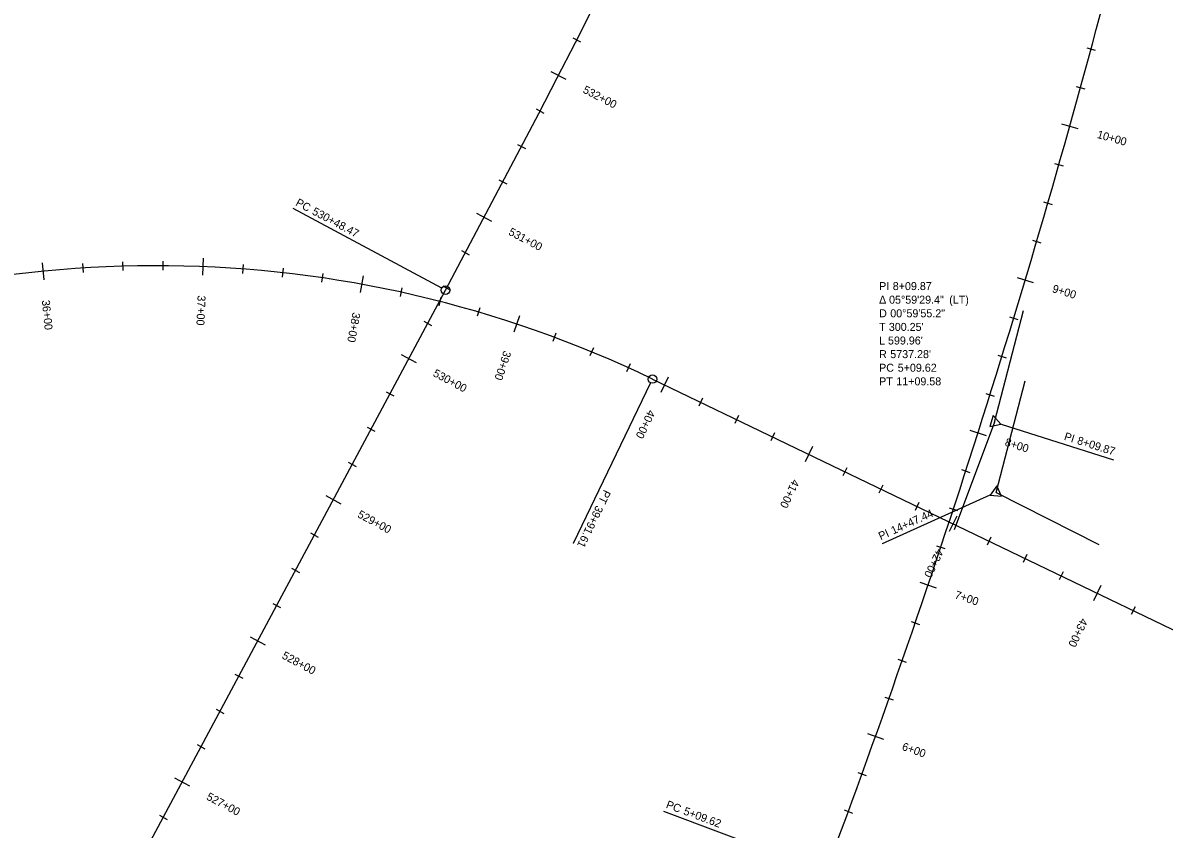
# Model space of a CAD drawing. Extents: x 2300830 to 2307917, y 756066 to 766359.
# Drawn here: x 2303533 to 2304246, y 761628 to 762132 of the extents above; entities that cross this region are included whole.
import ezdxf

# ---------------------------------------------------------------- set-up
doc = ezdxf.new("R2010")
doc.units = 0
for name, color, linetype in [('Default', 7, 'Continuous'), ('Draft_Curve Data Label', 7, 'Continuous'), ('Draft_Station Cardinal Lines', 7, 'Continuous'), ('Draft_Station Cardinal Points', 7, 'Continuous'), ('Draft_Station Labels Major', 7, 'Continuous'), ('Draft_Station Ticks Major', 7, 'Continuous'), ('Draft_Station Ticks Minor', 7, 'Continuous'), ('Geom_Baseline', 7, 'Continuous')]:
    doc.layers.add(name, color=color, linetype=linetype)

msp = doc.modelspace()

# ---------------------------------------------------------------- linework, layer by layer
at = {"layer": 'Default'}
for p, q in [((2301469.01, 757616.61), (2303797.09, 761964.97)), ((2301469.01, 757616.61), (2303797.09, 761964.97)), ((2303926.45, 761909.44), (2305518.87, 761142.43))]:
    msp.add_line(p, q, dxfattribs=at)
for centre, radius, start, end in [((2294501.04, 766942.01), 10544.55, 331.835697, 340.516399), ((2304169.7, 761693.02), 983.53, 137.61666, 272.52241), ((2298662.99, 763616.57), 5737.28, 339.437219, 345.42872), ((2303616.31, 761265.54), 714.7, 64.28167, 164.6807)]:
    msp.add_arc(centre, radius, start, end, dxfattribs=at)
at = {"layer": 'Draft_Station Cardinal Lines'}
for p, q in [((2303794.74, 761966.23), (2303701.88, 762015.94)), ((2304140.2, 761882.57), (2304158.31, 761952.25)), ((2303925.29, 761907.03), (2303876.98, 761806.73)), ((2304141.13, 761838.6), (2304159.25, 761908.29)), ((2304140.2, 761882.57), (2304114.91, 761815.16)), ((2304144.2, 761881.3), (2304214.56, 761859.03)), ((2304137.31, 761836.88), (2304070.03, 761806.54)), ((2304141.13, 761838.6), (2304205.36, 761806.05)), ((2304032.24, 761602.39), (2303933.62, 761639.38))]:
    msp.add_line(p, q, dxfattribs=at)
for points in [[(2304144.16, 761881.32), (2304139.3, 761886.63), (2304137.13, 761879.77)], [(2304137.34, 761836.89), (2304144.51, 761836.18), (2304141.55, 761842.74)]]:
    msp.add_lwpolyline(points, close=True, dxfattribs=at)
at = {"layer": 'Draft_Station Cardinal Points'}
for p, q in [((2303701.88, 762015.94), (2303701.88, 762015.94)), ((2303797.09, 761964.97), (2303797.09, 761964.97)), ((2303926.45, 761909.44), (2303926.45, 761909.44)), ((2304140.2, 761882.57), (2304140.2, 761882.57)), ((2304214.56, 761859.03), (2304214.56, 761859.03)), ((2304141.13, 761838.6), (2304141.13, 761838.6)), ((2303876.98, 761806.73), (2303876.98, 761806.73)), ((2304070.03, 761806.54), (2304070.03, 761806.54)), ((2303933.62, 761639.38), (2303933.62, 761639.38))]:
    msp.add_line(p, q, dxfattribs=at)
for centre in [(2303797.09, 761964.97), (2303926.45, 761909.44)]:
    msp.add_circle(centre, 2.67, dxfattribs=at)
at = {"layer": 'Draft_Station Ticks Major'}
for p, q in [((2303862.91, 762101.52), (2303872.34, 762096.64)), ((2304182.02, 762068.82), (2304192.24, 762065.95)), ((2303816.58, 762012.95), (2303825.97, 762007.98)), ((2303545.09, 761982.05), (2303546.14, 761971.48)), ((2303645.71, 761984.98), (2303645.28, 761974.37)), ((2303745.76, 761973.84), (2303743.85, 761963.4)), ((2304154.2, 761972.87), (2304164.38, 761969.82)), ((2303843.28, 761948.87), (2303839.93, 761938.79)), ((2303769.51, 761924.75), (2303778.87, 761919.74)), ((2303936.32, 761910.61), (2303931.72, 761901.04)), ((2304124.72, 761877.41), (2304134.84, 761874.19)), ((2304026.42, 761867.21), (2304021.81, 761857.65)), ((2303722.31, 761836.59), (2303731.67, 761831.58)), ((2304116.51, 761823.82), (2304111.9, 761814.25)), ((2304093.58, 761782.48), (2304103.64, 761779.08)), ((2304206.61, 761780.42), (2304202, 761770.86)), ((2303675.11, 761748.43), (2303684.47, 761743.42)), ((2304060.79, 761688.11), (2304070.79, 761684.54)), ((2303627.91, 761660.27), (2303637.27, 761655.26))]:
    msp.add_line(p, q, dxfattribs=at)
at = {"layer": 'Draft_Station Ticks Minor'}
for p, q in [((2303876.65, 762122.55), (2303881.56, 762120.02)), ((2304197.79, 762116.3), (2304203.11, 762114.86)), ((2304191.2, 762092.2), (2304196.52, 762090.73)), ((2303853.69, 762078.14), (2303858.59, 762075.6)), ((2303842.14, 762055.98), (2303847.03, 762053.42)), ((2304177.7, 762044.08), (2304183.01, 762042.57)), ((2303830.53, 762033.85), (2303835.41, 762031.28)), ((2304170.8, 762020.07), (2304176.1, 762018.53)), ((2304163.79, 761996.08), (2304169.08, 761994.52)), ((2303807.15, 761989.67), (2303812.02, 761987.07)), ((2303570.36, 761981.52), (2303570.71, 761976.02)), ((2303595.43, 761982.69), (2303595.59, 761977.18)), ((2303620.52, 761982.99), (2303620.49, 761977.47)), ((2303670.66, 761980.94), (2303670.24, 761975.43)), ((2303695.65, 761978.6), (2303695.04, 761973.11)), ((2303720.54, 761975.39), (2303719.73, 761969.92)), ((2303769.9, 761966.36), (2303768.72, 761960.97)), ((2303795.38, 761967.62), (2303800.25, 761965.01)), ((2303794.32, 761960.56), (2303792.95, 761955.22)), ((2303818.51, 761953.91), (2303816.96, 761948.62)), ((2303783.58, 761945.58), (2303788.45, 761942.97)), ((2304149.46, 761948.2), (2304154.74, 761946.6)), ((2303866.14, 761938.09), (2303864.22, 761932.92)), ((2303889.51, 761928.95), (2303887.4, 761923.84)), ((2304142.13, 761924.31), (2304147.41, 761922.68)), ((2303912.54, 761918.99), (2303910.26, 761913.96)), ((2303759.98, 761901.5), (2303764.85, 761898.89)), ((2304134.71, 761900.45), (2304139.98, 761898.8)), ((2303957.73, 761897.44), (2303955.33, 761892.46)), ((2303980.25, 761886.59), (2303977.86, 761881.61)), ((2303748.18, 761879.46), (2303753.05, 761876.85)), ((2304002.77, 761875.74), (2304000.38, 761870.76)), ((2303736.38, 761857.42), (2303741.25, 761854.81)), ((2304047.82, 761854.04), (2304045.43, 761849.07)), ((2304119.55, 761852.83), (2304124.8, 761851.14)), ((2304070.35, 761843.19), (2304067.95, 761838.22)), ((2304092.87, 761832.34), (2304090.47, 761827.37)), ((2304111.81, 761829.07), (2304117.05, 761827.35)), ((2303712.78, 761813.34), (2303717.65, 761810.73)), ((2304137.92, 761810.65), (2304135.52, 761805.67)), ((2304103.97, 761805.35), (2304109.21, 761803.6)), ((2304160.44, 761799.8), (2304158.04, 761794.82)), ((2303700.98, 761791.3), (2303705.85, 761788.69)), ((2304182.96, 761788.95), (2304180.57, 761783.98)), ((2303689.18, 761769.26), (2303694.05, 761766.65)), ((2304228.01, 761767.25), (2304225.61, 761762.28)), ((2304087.98, 761758), (2304093.2, 761756.21)), ((2304079.83, 761734.38), (2304085.04, 761732.57)), ((2303665.58, 761725.18), (2303670.45, 761722.57)), ((2304071.57, 761710.79), (2304076.78, 761708.96)), ((2303653.78, 761703.14), (2303658.65, 761700.53)), ((2303641.98, 761681.1), (2303646.85, 761678.49)), ((2304054.76, 761663.73), (2304059.95, 761661.85)), ((2303618.38, 761637.02), (2303623.25, 761634.41)), ((2304046.2, 761640.25), (2304051.38, 761638.35))]:
    msp.add_line(p, q, dxfattribs=at)
at = {"layer": 'Geom_Baseline'}
for p, q in [((2301469.01, 757616.61), (2303797.09, 761964.97)), ((2303926.45, 761909.44), (2305518.87, 761142.43))]:
    msp.add_line(p, q, dxfattribs=at)
for centre, radius, start, end in [((2294501.04, 766942.01), 10544.55, 331.835697, 340.516399), ((2304169.7, 761693.02), 983.53, 137.61666, 272.52241), ((2298662.99, 763616.57), 5737.28, 339.437219, 345.42872), ((2303616.31, 761265.54), 714.7, 64.28167, 164.6807)]:
    msp.add_arc(centre, radius, start, end, dxfattribs=at)

# ---------------------------------------------------------------- texts
at = {"layer": 'Draft_Curve Data Label'}
for s, p in [('PI ', (2304068.04, 761965)), ('8+09.87', (2304076.58, 761965)), ('Δ ', (2304068.04, 761956.5)), ('05°59\'29.4"', (2304074.26, 761956.5)), (' (LT)', (2304109.99, 761956.5)), ('D ', (2304068.04, 761948)), ('00°59\'55.2"', (2304075.02, 761948)), ('T ', (2304068.04, 761939.5)), ("300.25'", (2304074.12, 761939.5)), ('L ', (2304068.04, 761931)), ("599.96'", (2304073.6, 761931)), ('R ', (2304068.04, 761922.5)), ("5737.28'", (2304075.02, 761922.5)), ('PC ', (2304068.04, 761914)), ('5+09.62', (2304079.68, 761914)), ('PT ', (2304068.04, 761905.5)), ('11+09.58', (2304078.78, 761905.5))]:
    msp.add_text(s, height=5, dxfattribs=at).set_placement(p)
at = {"layer": 'Draft_Station Cardinal Points'}
for s, rotation, p in [('PC', 331.8357, (2303703.05, 762018.13)), ('530+48.47', 331.8357, (2303713.32, 762012.63)), ('PI ', 342.43297, (2304183.22, 761871.55)), ('8+09.87', 342.43297, (2304191.36, 761868.98)), ('PT', 244.28167, (2303896.1, 761840.7)), ('39+91.61', 244.28167, (2303891.38, 761830.91)), ('14+47.44', 24.27436, (2304076.83, 761812.24)), ('PI ', 24.27436, (2304069.04, 761808.72)), ('PC', 339.43722, (2303934.49, 761641.71)), ('5+09.62', 339.43722, (2303945.4, 761637.62))]:
    msp.add_text(s, height=5, rotation=rotation, dxfattribs=at).set_placement(p)
at = {"layer": 'Draft_Station Labels Major'}
for s, rotation, p in [('532+00', 332.65906, (2303882.49, 762088.57)), ('10+00', 344.33441, (2304203.81, 762060.11)), ('531+00', 332.11569, (2303836.04, 761999.82)), ('9+00', 343.33576, (2304175.85, 761963.78)), ('36+00', 275.67606, (2303544.91, 761958.57)), ('37+00', 267.65932, (2303642.26, 761961.76)), ('38+00', 259.64257, (2303739.1, 761951.33)), ('39+00', 251.62583, (2303833.55, 761927.51)), ('530+00', 331.8357, (2303788.9, 761911.53)), ('40+00', 244.28167, (2303923.94, 761890.67)), ('8+00', 342.3371, (2304146.2, 761867.95)), ('41+00', 244.28167, (2304014.04, 761847.27)), ('529+00', 331.8357, (2303741.7, 761823.37)), ('42+00', 244.28167, (2304104.13, 761803.88)), ('7+00', 341.33844, (2304114.89, 761772.65)), ('43+00', 244.28167, (2304194.22, 761760.48)), ('528+00', 331.8357, (2303694.5, 761735.21)), ('6+00', 340.33979, (2304081.93, 761677.9)), ('527+00', 331.8357, (2303647.3, 761647.05))]:
    msp.add_text(s, height=5, rotation=rotation, dxfattribs=at).set_placement(p)

doc.saveas('drawing.dxf')
